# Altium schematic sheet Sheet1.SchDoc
size A4
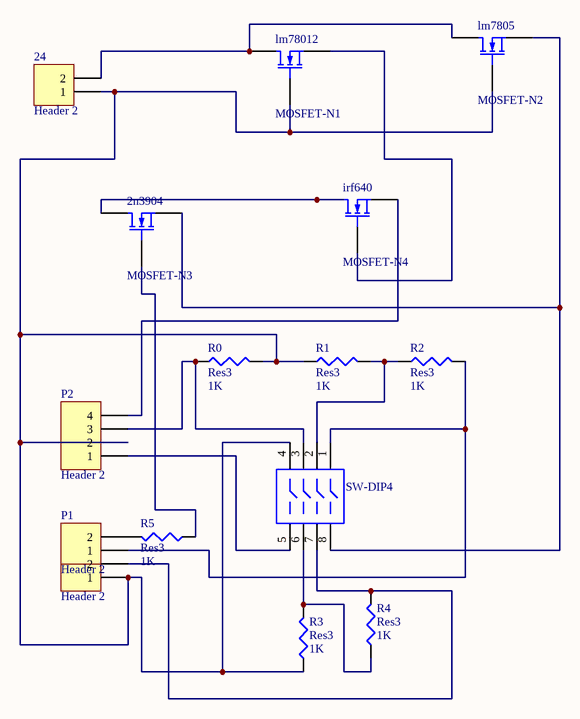
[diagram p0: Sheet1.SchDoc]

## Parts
2n3904  MOSFET-N3  [TO-92]
24  Header 2  [HDR1X2]
?  SW-DIP4  [MSOP-8]
irf640  MOSFET-N4  [TO-220-AB]
lm7805  MOSFET-N2  [TO-220-AB]
lm78012  MOSFET-N1  [TO-220-AB]
P0  Header 2  [HDR1X2]
P1  Header 2  [HDR1X2]
P2  Header 2  [HDR1X4]
R0  Res3  value 1K  [J1-0603]
R1  Res3  value 1K  [J1-0603]
R2  Res3  value 1K  [J1-0603]
R3  Res3  value 1K  [J1-0603]
R4  Res3  value 1K  [J1-0603]
R5  Res3  value 1K  [J1-0603]

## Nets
Net2n3904_1: 2n3904.1(D) irf640.1(D)
Net2n3904_2: 2n3904.2(G) R5.1
Net2n3904_3: 2n3904.3(S) ?.8 lm7805.3(S)
Net24_1: 24.1 ?.4 lm7805.2(G) lm78012.2(G) P0.1 P2.2 R0.2 R1.1 R3.1
Net24_2: 24.2 lm7805.1(D) lm78012.1(D)
Net?_1: ?.1 P1.1 R2.2
Net?_2: ?.2 R1.2 R2.1
Net?_3: ?.3 P2.3 R0.1
Net?_5: ?.5 P2.1
Net?_6: ?.6 R3.2 R4.1
Net?_7: ?.7 P0.2 R4.2
Netirf640_2: irf640.2(G) lm78012.3(S)
Netirf640_3: irf640.3(S) P2.4
NetP1_2: P1.2 R5.2

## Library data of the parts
2n3904 irf640 lm7805 lm78012 = MOSFET-N: N-Channel MOSFET
24 P0 P1 = Header 2: Header, 2-Pin
? = SW-DIP4: DIP Switch
P2 = Header 4: Header, 4-Pin
R0-R5 = Res3: Resistor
